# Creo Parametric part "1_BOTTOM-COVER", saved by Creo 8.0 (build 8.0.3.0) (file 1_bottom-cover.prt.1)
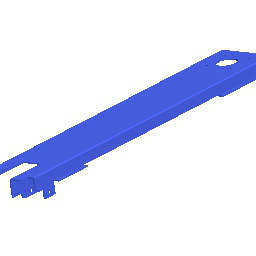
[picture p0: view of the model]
Units: millimeter Newton Second (mmNs); MM, TONNE, SECS

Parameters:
  SMT_DFLT_BEND_REL_LENGTH_TYPE = "Through All"

Other parameters: SMT_THICKNESS, SMT_PART_BEND_ALLOWANCE_FACTOR, SMT_DFLT_BEND_RADIUS, SMT_DFLT_BEND_ANGLE, SMT_DFLT_CRNR_REL_WIDTH, SMT_DFLT_CRNR_REL_DEPTH, SMT_DFLT_BEND_REL_WIDTH, SMT_DFLT_BEND_REL_DEPTH, SMT_DFLT_BEND_REL_LENGTH, SMT_DFLT_BEND_REL_ANGLE, SMT_GAP, SMT_DFLT_EDGE_TREA_WIDTH, SMT_DFLT_MITER_CUT_WIDTH, SMT_DFLT_MITER_CUT_OFFSET

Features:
  1. datum plane "DTM4"
  2. datum plane "DTM5"
  3. datum plane "DTM6"
  4. datum plane "DTM7"
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
Other named items: COPIED_GROUP

Layers: 0_ALL_AXIS, 0_ALL_CSYS, 0_ALL_CURVES, 0_ALL_PLANES, 0_ALL_POINTS, 0_ALL_SURFS, BOTTOM-COVER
